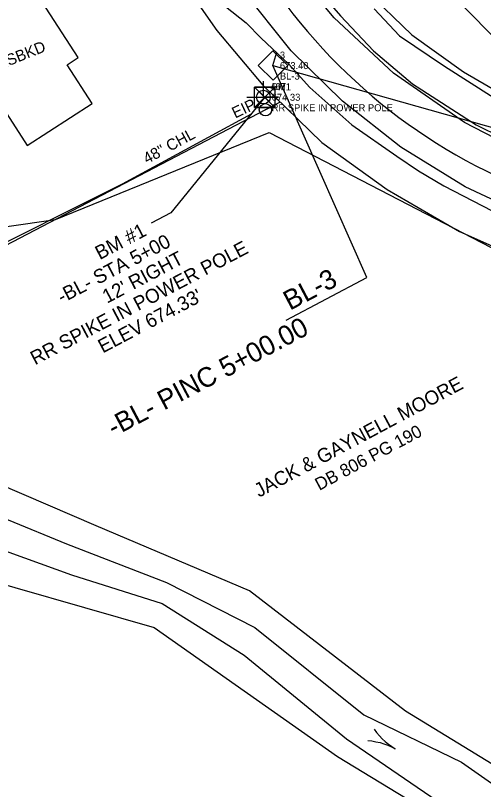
# Model space of a CAD drawing. Extents: x 1380524 to 1382335, y 594765 to 596944.
# Drawn here: x 1381171.1 to 1381338.3, y 595253.4 to 595529.8 of the extents above; entities that cross this region are included whole.
import ezdxf

# ---------------------------------------------------------------- set-up
doc = ezdxf.new("R2010")
doc.units = 0
for name, color, linetype in [('CTL Bench Mark CELL', 7, 'Continuous'), ('CTL Bench Mark Cogo Comment', 7, 'Continuous'), ('CTL Bench Mark Cogo Elevation', 7, 'Continuous'), ('CTL Bench Mark Cogo Number', 7, 'Continuous'), ('CTL Bench Mark Leader', 7, 'Continuous'), ('CTL Bench Mark Text', 7, 'Continuous'), ('CTL Supplemental Horizontal and Vertical Cogo Comment', 7, 'Continuous'), ('CTL Supplemental Horizontal and Vertical Cogo Elevation', 7, 'Continuous'), ('DTM Contours Minor Text', 7, 'Continuous'), ('Exist Horizontal Alignment', 7, 'Continuous'), ('Exist Horizontal Baseline Alignment', 7, 'Continuous'), ('Exist Horizontal Baseline Alignment Station Label', 7, 'Continuous'), ('Exist Horizontal Baseline Alignment Tick small', 7, 'Continuous'), ('Exist Hydro Jurisdictional Stream or Body of Water', 7, 'Continuous'), ('Exist Other Culture Fence Line', 7, 'Continuous'), ('Exist Right of Way Line', 7, 'Continuous'), ('Exist Roads EOP', 7, 'Continuous'), ('Exist Roads Soil', 7, 'Continuous'), ('Exist Structure Major Deck Tunnel Box Culvert', 7, 'Continuous'), ('Exist Structure Minor Pipes CMP 18 Inch', 7, 'Continuous'), ('Exist Utilities Gas UG Line SUE Text', 7, 'Continuous'), ('Exist Utilities Power Tower Text', 7, 'Continuous'), ('Exist Utilities Telephone UG Cable', 7, 'Continuous'), ('Exist Vegetation Tree CELL', 7, 'Continuous'), ('Prop Approach Slab', 7, 'Continuous'), ('Prop Approach Slab Hatching', 7, 'Continuous'), ('Prop Drainage Ditch Base Lines', 7, 'Continuous'), ('Prop Earthen Structure Cut Ditch Special Detail Label', 7, 'Continuous'), ('Prop Earthen Structure Ditch Flow Line', 7, 'Continuous'), ('Prop Earthen Structure V Ditch Lateral Detail Label', 7, 'Continuous'), ('Prop Plan Preparation Design Box Number Symbol CELL', 7, 'Continuous'), ('Prop SS Cut Line', 7, 'Continuous'), ('Prop SS Transition Line', 7, 'Continuous'), ('Scratch_Level_6', 7, 'Continuous')]:
    doc.layers.add(name, color=color, linetype=linetype)

# ---------------------------------------------------------------- blocks, each defined once
blk = doc.blocks.new('EXIST HYDRO STREAM FLOW ARROW')
at = {"layer": 'DTM Contours Minor Text'}
blk.add_line((0, 0), (0, 0), dxfattribs=at)
for points in [[(-0.1, 0.04575), (-0.07325, 0.03375), (-0.04475, 0.0245), (-0.0165, 0.01575), (0.01175, 0.0095), (0.041, 0.00475), (0.07075, 0.0015), (0.1, 0)], [(-0.1, -0.04575), (-0.07325, -0.03375), (-0.04475, -0.0245), (-0.0165, -0.01575), (0.01175, -0.0095), (0.041, -0.00475), (0.07075, -0.0015), (0.1, 0)]]:
    blk.add_lwpolyline(points, dxfattribs=at)
blk = doc.blocks.new('EXIST UTILITIES POWER JOINT USE TELEPHONE')
at = {"layer": 'Exist Utilities Gas UG Line SUE Text'}
blk.add_line((0, 0), (0, 0), dxfattribs=at)
blk.add_lwpolyline([(-0.1188, 0), (0.108, -0.0008), (0, -0.0004), (0, 0.1125)], dxfattribs=at)
blk.add_circle((0, 0.0001), 0.049, dxfattribs=at)

msp = doc.modelspace()

# ---------------------------------------------------------------- linework, layer by layer
at = {"layer": 'CTL Bench Mark CELL'}
msp.add_line((1381260.17, 595500.64), (1381260.17, 595500.64), dxfattribs=at)
msp.add_lwpolyline([(1381256.57, 595504.23), (1381263.75, 595504.23), (1381263.75, 595497.04), (1381256.57, 595497.04)], close=True, dxfattribs=at)
for points in [[(1381263.75, 595504.23), (1381256.57, 595497.04), (1381260.16, 595500.64), (1381263.75, 595497.04), (1381256.57, 595504.23)], [(1381260.16, 595500.64), (1381263.75, 595504.23), (1381256.57, 595504.23), (1381260.16, 595500.64)], [(1381260.16, 595500.64), (1381256.57, 595497.04), (1381263.75, 595497.04), (1381260.16, 595500.64)]]:
    msp.add_lwpolyline(points, dxfattribs=at)
at = {"layer": 'CTL Bench Mark Leader'}
msp.add_lwpolyline([(1381260.17, 595500.64), (1381226.61, 595459.36), (1381219.64, 595455.68)], dxfattribs=at)
at = {"layer": 'Exist Horizontal Alignment'}
msp.add_arc((1381427.83, 595653.65), 200, 216.8315, 254.276, dxfattribs=at)
msp.add_arc((1381427.83, 595653.65), 200, 216.8315, 254.276, dxfattribs=at)
msp.add_arc((1381427.83, 595653.65), 200, 216.8315, 254.276, dxfattribs=at)
at = {"layer": 'Exist Horizontal Baseline Alignment'}
msp.add_line((1381263.09, 595511.94), (1381525.59, 595437.8), dxfattribs=at)
at = {"layer": 'Exist Horizontal Baseline Alignment Station Label'}
for p, q in [((1381296.6, 595436.22), (1381263.09, 595511.94)), ((1381267.86, 595421.07), (1381296.6, 595436.22))]:
    msp.add_line(p, q, dxfattribs=at)
at = {"layer": 'Exist Horizontal Baseline Alignment Tick small'}
msp.add_line((1381263.09, 595511.94), (1381264.45, 595516.76), dxfattribs=at)
at = {"layer": 'Exist Hydro Jurisdictional Stream or Body of Water'}
for points in [[(1380985.02, 595366.88), (1381014.08, 595367.37), (1381042.38, 595363.3), (1381053.08, 595379.87), (1381083.61, 595386.57), (1381110.12, 595387.98), (1381133.86, 595373.94), (1381147.55, 595358.23), (1381189.33, 595341.18), (1381225.05, 595327.29), (1381256.58, 595311.26), (1381295.63, 595280.09), (1381330.47, 595263.19), (1381357.79, 595244.04), (1381403.48, 595232.23), (1381443.85, 595221.49), (1381471.36, 595213.42), (1381497.44, 595202.53)], [(1380984.33, 595345.39), (1381012.4, 595345.16), (1381050.02, 595351.98), (1381062.33, 595372.25), (1381087.24, 595376.82), (1381108.4, 595376.6), (1381128, 595367.34), (1381141.96, 595347.82), (1381191.15, 595330.13), (1381223.59, 595319.8), (1381252.88, 595301.34), (1381289.39, 595271.54), (1381324.06, 595247.84), (1381354.14, 595234.28), (1381401.64, 595222.35), (1381444.7, 595211.31), (1381465.95, 595205.87), (1381493.22, 595194.98)]]:
    msp.add_lwpolyline(points, dxfattribs=at)
at = {"layer": 'Exist Other Culture Fence Line'}
for q in [(1381259.69, 595506.33), (1381259.69, 595506.33), (1381259.69, 595500.7), (1381259.69, 595500.7)]:
    msp.add_line((1381259.69, 595500.7), q, dxfattribs=at)
msp.add_circle((1381259.69, 595500.7), 2.45, dxfattribs=at)
msp.add_circle((1381259.69, 595500.7), 2.45, dxfattribs=at)
at = {"layer": 'Exist Roads EOP'}
for points in [[(1381161.15, 595696), (1381164.06, 595686.12), (1381174.18, 595656.96), (1381185.71, 595627.95), (1381196.46, 595603.62), (1381208.77, 595578.34), (1381225.25, 595550.12), (1381243.05, 595524.53), (1381259.54, 595504.93), (1381280.57, 595484.48), (1381303.91, 595467.71), (1381329.76, 595452.68), (1381358.42, 595440), (1381388.14, 595431.06), (1381418.93, 595425.53), (1381449.98, 595423.57), (1381478.51, 595424.07), (1381493.32, 595424.85)], [(1381231.86, 595647.22), (1381241.81, 595624.69), (1381252.89, 595601.94), (1381267.43, 595577.05), (1381282.78, 595554.97), (1381296.18, 595539.04), (1381312.76, 595522.92), (1381331.13, 595509.71), (1381352.52, 595497.29), (1381375.81, 595486.97), (1381399.82, 595479.76), (1381424.98, 595475.23), (1381451.15, 595473.58), (1381476.8, 595474.04), (1381490.75, 595474.77)]]:
    msp.add_lwpolyline(points, dxfattribs=at)
at = {"layer": 'Exist Utilities Power Tower Text'}
for p, q in [((1381265.71, 595498.93), (1381260.44, 595496.18)), ((1381260.44, 595496.18), (1381100.61, 595412.76))]:
    msp.add_line(p, q, dxfattribs=at)
at = {"layer": 'Exist Utilities Telephone UG Cable'}
for p, q in [((1381281.43, 595536.44), (1381287.19, 595529.71)), ((1381246.19, 595533.02), (1381253.49, 595527.28)), ((1381299.22, 595532.27), (1381308.3, 595522.57)), ((1381287.19, 595529.71), (1381299.06, 595517.26)), ((1381253.49, 595527.28), (1381258.85, 595521.72)), ((1381258.85, 595521.72), (1381268.71, 595512.58)), ((1381308.3, 595522.57), (1381324.33, 595511.79)), ((1381299.06, 595517.26), (1381312.93, 595505.46)), ((1381268.71, 595512.58), (1381276.33, 595504.17)), ((1381324.33, 595511.79), (1381342.18, 595500.41)), ((1381276.33, 595504.17), (1381291.32, 595490.81)), ((1381312.93, 595505.46), (1381335.74, 595490.85)), ((1381291.32, 595490.81), (1381307.34, 595479.6)), ((1381335.74, 595490.85), (1381365.58, 595475.87)), ((1381307.34, 595479.6), (1381315.1, 595474.33)), ((1381315.1, 595474.33), (1381324.11, 595469)), ((1381324.11, 595469), (1381348.99, 595456.07))]:
    msp.add_line(p, q, dxfattribs=at)
at = {"layer": 'Prop Drainage Ditch Base Lines'}
msp.add_lwpolyline([(1381142.98, 595533.61), (1381175.33, 595483.46), (1381198.57, 595498.46), (1381189.65, 595512.28), (1381193.58, 595514.81), (1381179.3, 595537), (1381175.5, 595534.56), (1381166.4, 595548.69)], close=True, dxfattribs=at)
at = {"layer": 'Prop Earthen Structure Cut Ditch Special Detail Label'}
for points in [[(1381311.01, 595552.25), (1381321.59, 595588.1), (1381354.11, 595565.54), (1381373.79, 595564.89), (1381382.69, 595595.08), (1381416.12, 595616.7), (1381418.47, 595677.64), (1381445.54, 595666.13), (1381483.46, 595545.08), (1381491.42, 595475.89), (1381457.51, 595475.03), (1381424.36, 595495.63), (1381355.51, 595508.44), (1381311.33, 595553.4)], [(1380970.1, 595427.87), (1381024.06, 595422.83), (1381114.96, 595446.92), (1381185.45, 595457.03), (1381261.8, 595488.06), (1381347.51, 595443.64), (1381414.83, 595426.48), (1381476.71, 595423.61), (1381522.74, 595425.41), (1381550.61, 595301.49), (1381576.12, 595225.45)], [(1381503.34, 595209.65), (1381437.89, 595231.26), (1381360.06, 595251.07), (1381310.4, 595281.34), (1381254.74, 595324.36), (1381199.97, 595347.63), (1381147.52, 595370.02), (1381108.16, 595398.49), (1381050.18, 595388.66), (1381033.41, 595371.94), (1380985.64, 595374.68)], [(1380986.69, 595338.75), (1381055.98, 595344.99), (1381070.91, 595366.1), (1381119.38, 595362.42), (1381145.86, 595332.73), (1381220.72, 595311.21), (1381286.15, 595265.22), (1381335.39, 595235.31), (1381397.02, 595214.43), (1381459.67, 595198.28)]]:
    msp.add_lwpolyline(points, dxfattribs=at)
at = {"layer": 'Prop Earthen Structure Ditch Flow Line'}
for points in [[(1381491.33, 595459.68), (1381464.85, 595458.25), (1381435.67, 595459.27), (1381408.13, 595463.04), (1381381.89, 595469.34), (1381356.9, 595478.55), (1381331.5, 595491.59), (1381306.2, 595509.27), (1381284.93, 595529.02), (1381267.78, 595549.61), (1381247.25, 595580.06), (1381224.31, 595624.91), (1381211.16, 595655.93), (1381195.13, 595701.47), (1381187.72, 595727.78)], [(1381492.25, 595440), (1381464.79, 595438.13), (1381437.85, 595438.71), (1381408.74, 595442.02), (1381381.18, 595448.34), (1381355.66, 595457.45), (1381331.8, 595468.68), (1381308.83, 595482.8), (1381287.93, 595499.23), (1381269.66, 595517.22), (1381252.13, 595539.26), (1381236.19, 595562.85), (1381220.35, 595591.19), (1381206.28, 595620.98), (1381194.7, 595648.28), (1381177.83, 595693.24), (1381172.27, 595703.71), (1381163.83, 595709.25)]]:
    msp.add_lwpolyline(points, dxfattribs=at)
at = {"layer": 'Prop Earthen Structure V Ditch Lateral Detail Label'}
msp.add_lwpolyline([(1381255.28, 595494.61), (1381209.21, 595469.63), (1381153.47, 595441.77), (1381102.94, 595414.54), (1381098.51, 595412.2), (1381067.82, 595481.71), (1381046.81, 595525.39), (1381069.79, 595537.28)], dxfattribs=at)
at = {"layer": 'Prop SS Cut Line'}
msp.add_line((1381263.09, 595511.94), (1381263.09, 595511.94), dxfattribs=at)
msp.add_lwpolyline([(1381257.88, 595511.96), (1381263.12, 595517.2), (1381268.37, 595511.95), (1381263.13, 595506.71)], close=True, dxfattribs=at)
at = {"layer": 'Prop SS Transition Line'}
for radius in [2.2, 0.0707]:
    msp.add_circle((1381260.44, 595496.18), radius, dxfattribs=at)

# ---------------------------------------------------------------- block references
at = {"layer": 'Exist Utilities Gas UG Line SUE Text', "xscale": 50, "yscale": 50}
msp.add_blockref('EXIST UTILITIES POWER JOINT USE TELEPHONE', (1381259.69, 595500.7), dxfattribs=at)
at = {"layer": 'Prop Plan Preparation Design Box Number Symbol CELL', "xscale": 50, "yscale": 50, "rotation": -29.55326944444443}
msp.add_blockref('EXIST HYDRO STREAM FLOW ARROW', (1381302.46, 595270.44), dxfattribs=at)

# ---------------------------------------------------------------- texts
at = {"layer": 'CTL Bench Mark Cogo Comment'}
msp.add_text('RR SPIKE IN POWER POLE', height=2.5, dxfattribs=at).set_placement((1381262.67, 595495.64))
at = {"layer": 'CTL Bench Mark Cogo Elevation'}
msp.add_text('674.33', height=2.5, dxfattribs=at).set_placement((1381262.67, 595499.39))
at = {"layer": 'CTL Bench Mark Cogo Number'}
msp.add_text('BM1', height=2.5, dxfattribs=at).set_placement((1381262.67, 595503.14))
at = {"layer": 'CTL Bench Mark Text'}
for s, p in [('BM #1 ', (1381201.25, 595442.46)), ('-BL- STA 5+00', (1381187.74, 595426.87)), ('RR SPIKE IN POWER POLE ', (1381178.13, 595404.86)), ("12' RIGHT", (1381203.84, 595426.88)), ("ELEV 674.33' ", (1381202.3, 595409.11))]:
    msp.add_text(s, height=5, rotation=27.7685, dxfattribs=at).set_placement(p)
at = {"layer": 'CTL Supplemental Horizontal and Vertical Cogo Comment'}
msp.add_text('BL-3', height=2.5, dxfattribs=at).set_placement((1381265.59, 595506.95))
at = {"layer": 'CTL Supplemental Horizontal and Vertical Cogo Elevation'}
msp.add_text('673.40', height=2.5, dxfattribs=at).set_placement((1381265.59, 595510.7))
at = {"layer": 'Exist Horizontal Baseline Alignment Station Label'}
msp.add_text('BL-3', height=7, rotation=27.7977, dxfattribs=at).set_placement((1381269.18, 595424.37))
at = {"layer": 'Exist Right of Way Line'}
msp.add_text('JACK & GAYNELL MOORE', height=5, rotation=28.1231, dxfattribs=at).set_placement((1381258.13, 595357.58))
at = {"layer": 'Exist Roads Soil'}
msp.add_text('3', height=2.5, dxfattribs=at).set_placement((1381265.59, 595514.45))
at = {"layer": 'Exist Structure Major Deck Tunnel Box Culvert'}
msp.add_text('EIP', height=4, rotation=25.2286, dxfattribs=at).set_placement((1381249.62, 595493.02))
at = {"layer": 'Exist Structure Minor Pipes CMP 18 Inch'}
msp.add_text('DB 806 PG 190', height=4.5, rotation=28.1231, dxfattribs=at).set_placement((1381279.65, 595360.04))
at = {"layer": 'Exist Vegetation Tree CELL'}
msp.add_text('467', height=2.5, dxfattribs=at).set_placement((1381262.19, 595503.2))
msp.add_text('467', height=2.5, dxfattribs=at).set_placement((1381262.19, 595503.2))
at = {"layer": 'Prop Approach Slab'}
msp.add_text('1SBKD', height=4, rotation=21.8779, dxfattribs=at).set_placement((1381166.05, 595510.68))
at = {"layer": 'Prop Approach Slab Hatching'}
msp.add_text('48" CHL', height=4, rotation=28.4707, dxfattribs=at).set_placement((1381218.1, 595476.72))
at = {"layer": 'Scratch_Level_6'}
msp.add_text('-BL- PINC 5+00.00 ', height=7, rotation=27.7977, dxfattribs=at).set_placement((1381206.24, 595379.25))

doc.saveas('drawing.dxf')
